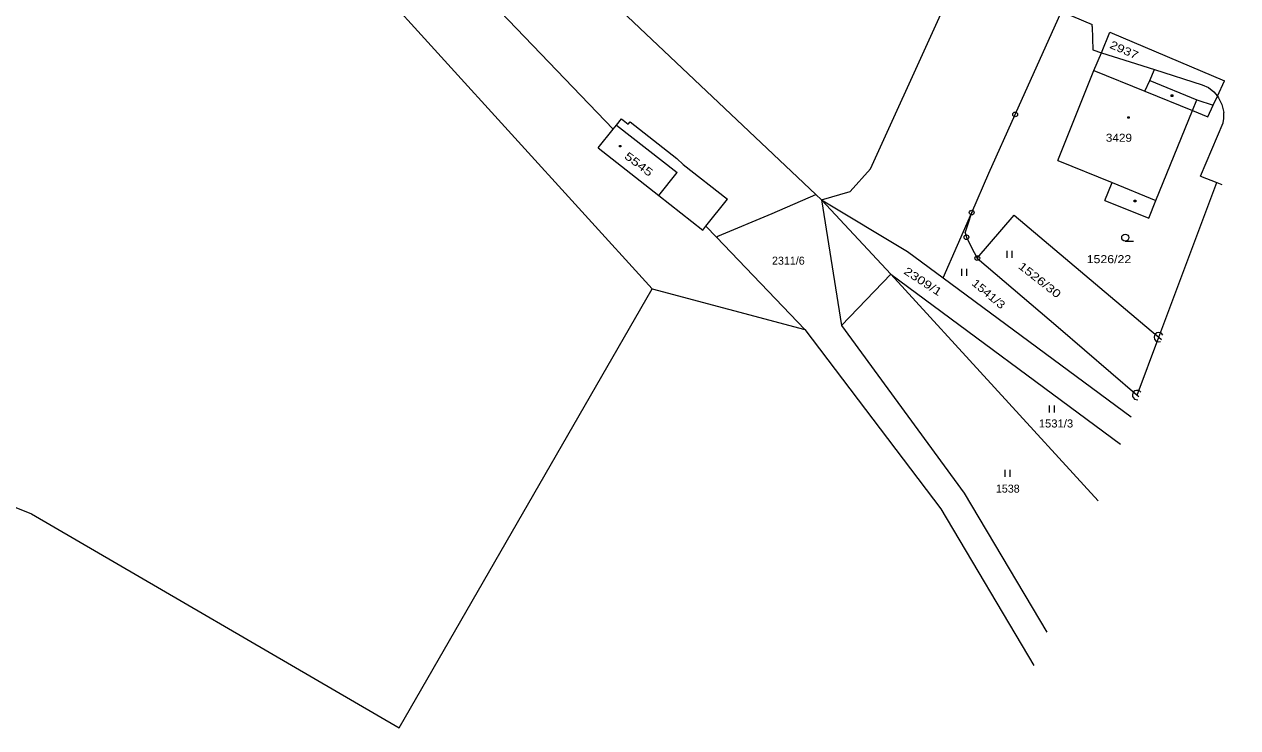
# Model space of a CAD drawing. Extents: x -630464 to -630140, y -1004543 to -1004208.
# Drawn here: x -630338.9 to -630210, y -1004542.6 to -1004467.8 of the extents above; entities that cross this region are included whole.
import ezdxf

# ---------------------------------------------------------------- set-up
doc = ezdxf.new("R2010")
doc.units = 0
doc.header["$LTSCALE"] = 0.34
for name, color, linetype, lineweight in [('1', 7, 'Continuous', 13), ('2', 7, 'Continuous', 13), ('23', 7, 'Continuous', 13), ('25', 7, 'Continuous', 13), ('28', 7, 'Continuous', 13)]:
    doc.layers.add(name, color=color, linetype=linetype, lineweight=lineweight)
doc.layers.add('14', color=7, linetype='Continuous')
doc.layers.add('15', color=7, linetype='Continuous')

msp = doc.modelspace()

# ---------------------------------------------------------------- linework, layer by layer
at = {"layer": '1'}
for p, q in [((-630233.63, -1004477.39), (-630228.7, -1004466.46)), ((-630228.7, -1004466.46), (-630225.45, -1004467.84)), ((-630225.45, -1004468.06), (-630225.45, -1004467.84)), ((-630212.15, -1004475.46), (-630211.39, -1004473.83)), ((-630236.41, -1004483.63), (-630233.63, -1004477.39)), ((-630213.94, -1004483.95), (-630211.55, -1004478.27)), ((-630229.09, -1004482.28), (-630223.34, -1004484.62)), ((-630224.11, -1004486.52), (-630223.34, -1004484.62)), ((-630218.38, -1004501.06), (-630212.21, -1004484.62)), ((-630213.94, -1004483.95), (-630212.21, -1004484.62)), ((-630212.21, -1004484.62), (-630211.666, -1004484.83)), ((-630266.48, -1004489.27), (-630264.18, -1004486.38)), ((-630254.2, -1004486.47), (-630245.06, -1004491.94)), ((-630241.28, -1004494.74), (-630238.25, -1004487.82)), ((-630237.65, -1004492.65), (-630233.74, -1004488.08)), ((-630245.06, -1004491.94), (-630241.28, -1004494.74)), ((-630237.65, -1004492.65), (-630229.08, -1004500)), ((-630252.08, -1004499.81), (-630246.82, -1004494.36)), ((-630246.82, -1004494.36), (-630222.448, -1004512.408)), ((-630246.82, -1004494.36), (-630224.814, -1004518.459)), ((-630241.28, -1004494.74), (-630221.318, -1004509.517)), ((-630229.08, -1004500), (-630220.68, -1004507.2)), ((-630220.68, -1004507.2), (-630218.38, -1004501.06)), ((-630218.38, -1004501.06), (-630218.103, -1004501.294)), ((-630220.68, -1004507.2), (-630220.479, -1004507.372)), ((-630239.03, -1004517.62), (-630230.264, -1004532.398)), ((-630241.52, -1004519.3), (-630231.649, -1004535.941))]:
    msp.add_line(p, q, dxfattribs=at)
for points in [[(-630360.7, -1004381.74), (-630343.98, -1004399.94), (-630338.03, -1004406.42), (-630333.23, -1004411.18), (-630324.32, -1004420.02), (-630324.04, -1004420.28), (-630303.74, -1004439.53), (-630293.73, -1004449.03), (-630288.99, -1004453.52), (-630254.82, -1004485.91)], [(-630254.2, -1004486.47), (-630251.14, -1004485.59), (-630248.99, -1004483.18), (-630220.7, -1004420.89), (-630209.99, -1004425.12)], [(-630324.95, -1004437.86), (-630324.49, -1004438.36), (-630272.19, -1004495.93)], [(-630312.18, -1004442.41), (-630310.52, -1004443.29), (-630276.34, -1004478.97)], [(-630225.45, -1004468.06), (-630225.42, -1004469.33), (-630225.39, -1004470.54), (-630224.46, -1004470.83)], [(-630224.46, -1004470.83), (-630223.58, -1004468.64), (-630211.39, -1004473.83)], [(-630229.09, -1004482.28), (-630225.27, -1004472.72), (-630224.46, -1004470.83), (-630221.41, -1004471.8)], [(-630221.41, -1004471.8), (-630218.82, -1004472.62), (-630213.77, -1004474.23), (-630213.11, -1004474.54), (-630212.54, -1004474.99), (-630212.15, -1004475.46)], [(-630213.16, -1004477.65), (-630212.59, -1004476.42), (-630212.15, -1004475.46), (-630212.02, -1004475.61), (-630211.67, -1004476.32), (-630211.47, -1004477.19)], [(-630224.11, -1004486.52), (-630219.45, -1004488.41), (-630218.68, -1004486.52), (-630214.8, -1004476.98), (-630213.16, -1004477.65)], [(-630277.93, -1004480.93), (-630276.34, -1004478.97), (-630275.98, -1004478.53), (-630275.46, -1004477.86), (-630274.74, -1004478.43), (-630274.51, -1004478.16), (-630269.55, -1004482.08), (-630268.89, -1004482.7), (-630264.18, -1004486.38)], [(-630211.55, -1004478.27), (-630211.48, -1004477.83), (-630211.47, -1004477.19)], [(-630277.93, -1004480.93), (-630271.47, -1004486), (-630266.82, -1004489.7), (-630266.48, -1004489.27), (-630265.36, -1004490.43), (-630255.97, -1004500.24)], [(-630238.93, -1004489.97), (-630238.62, -1004489.02), (-630238.25, -1004487.82), (-630236.41, -1004483.63)], [(-630437.56, -1004485.94), (-630403.49, -1004499.4), (-630362.22, -1004510.15), (-630338.12, -1004519.84), (-630299.05, -1004542.55), (-630272.19, -1004495.93), (-630255.97, -1004500.24), (-630241.52, -1004519.3)], [(-630265.36, -1004490.43), (-630265.2, -1004490.33), (-630259.45, -1004487.91), (-630254.82, -1004485.91), (-630254.2, -1004486.47), (-630252.08, -1004499.81), (-630239.03, -1004517.62)], [(-630233.74, -1004488.08), (-630219.17, -1004500.39), (-630218.38, -1004501.06)], [(-630238.93, -1004489.97), (-630238.8, -1004490.43), (-630238.3, -1004491.46), (-630237.65, -1004492.65)]]:
    msp.add_lwpolyline(points, dxfattribs=at)
at = {"layer": '2'}
for p, q in [((-630225.27, -1004472.72), (-630219.85, -1004474.93)), ((-630219.34, -1004473.78), (-630218.82, -1004472.62)), ((-630219.85, -1004474.93), (-630219.34, -1004473.78)), ((-630219.34, -1004473.78), (-630214.33, -1004475.82)), ((-630219.85, -1004474.93), (-630214.8, -1004476.98)), ((-630214.8, -1004476.98), (-630214.33, -1004475.82)), ((-630214.33, -1004475.82), (-630212.59, -1004476.42)), ((-630275.98, -1004478.53), (-630269.54, -1004483.57)), ((-630271.47, -1004486), (-630269.54, -1004483.57)), ((-630223.34, -1004484.62), (-630218.68, -1004486.52)), ((-630254.2, -1004486.47), (-630246.82, -1004494.36))]:
    msp.add_line(p, q, dxfattribs=at)
at = {"layer": '23'}
for p, q in [((-630221.94, -1004490.85), (-630221.065, -1004490.85)), ((-630234.48, -1004492.62), (-630234.48, -1004491.87)), ((-630233.98, -1004491.87), (-630233.98, -1004492.62)), ((-630239.31, -1004494.54), (-630239.31, -1004493.79)), ((-630238.81, -1004493.79), (-630238.81, -1004494.54)), ((-630229.97, -1004509.06), (-630229.97, -1004508.31)), ((-630229.47, -1004508.31), (-630229.47, -1004509.06)), ((-630234.7, -1004515.9), (-630234.7, -1004515.15)), ((-630234.2, -1004515.15), (-630234.2, -1004515.9))]:
    msp.add_line(p, q, dxfattribs=at)
msp.add_circle((-630221.94, -1004490.475), 0.375, dxfattribs=at)
at = {"layer": '25'}
for points in [[(-630217.05, -1004475.32), (-630216.9, -1004475.32), (-630216.9, -1004475.47), (-630217.05, -1004475.47)], [(-630221.66, -1004477.63), (-630221.51, -1004477.63), (-630221.51, -1004477.78), (-630221.66, -1004477.78)], [(-630275.66, -1004480.69), (-630275.51, -1004480.69), (-630275.51, -1004480.84), (-630275.66, -1004480.84)], [(-630220.98, -1004486.51), (-630220.83, -1004486.51), (-630220.83, -1004486.66), (-630220.98, -1004486.66)]]:
    msp.add_lwpolyline(points, close=True, dxfattribs=at)
at = {"layer": '28'}
for centre, radius in [((-630233.63, -1004477.39), 0.25), ((-630233.63, -1004477.39), 0.005), ((-630238.25, -1004487.82), 0.25), ((-630238.25, -1004487.82), 0.005), ((-630238.8, -1004490.43), 0.25), ((-630238.8, -1004490.43), 0.005), ((-630237.65, -1004492.65), 0.25), ((-630237.65, -1004492.65), 0.005), ((-630218.38, -1004501.06), 0.01), ((-630220.68, -1004507.2), 0.01)]:
    msp.add_circle(centre, radius, dxfattribs=at)
for centre, start, end in [((-630218.38, -1004501.06), 25.25259, 292.03856), ((-630220.68, -1004507.2), 38.67217, 278.61897)]:
    msp.add_arc(centre, 0.5, start, end, dxfattribs=at)

# ---------------------------------------------------------------- texts
at = {"layer": '14'}
for s, rotation, width, p in [('2937', 336.313, 1.25, (-630223.67, -1004470.29)), ('2309/1', 326.861, 1.3, (-630245.55, -1004494.25)), ('1526/30', 321.794, 1.3, (-630233.38, -1004493.66)), ('1541/3', 319.937, 1.2, (-630238.32, -1004495.44))]:
    msp.add_text(s, height=0.85, rotation=rotation, dxfattribs=dict(at, width=width)).set_placement(p)
for s, p in [('2311/6', (-630259.46, -1004493.35)), ('1538', (-630235.68, -1004517.57))]:
    msp.add_text(s, height=0.85, dxfattribs=at).set_placement(p)
for s, width, p in [('1526/22', 1.15, (-630226.03, -1004493.19)), ('1531/3', 1.05, (-630231.12, -1004510.65))]:
    msp.add_text(s, height=0.85, dxfattribs=dict(at, width=width)).set_placement(p)
at = {"layer": '15', "width": 1.1}
msp.add_text('3429', height=0.85, dxfattribs=at).set_placement((-630224, -1004480.29))
at = {"layer": '15', "width": 1.35}
msp.add_text('5545', height=0.85, rotation=322.828, dxfattribs=at).set_placement((-630275.22, -1004481.98))

doc.saveas('drawing.dxf')
